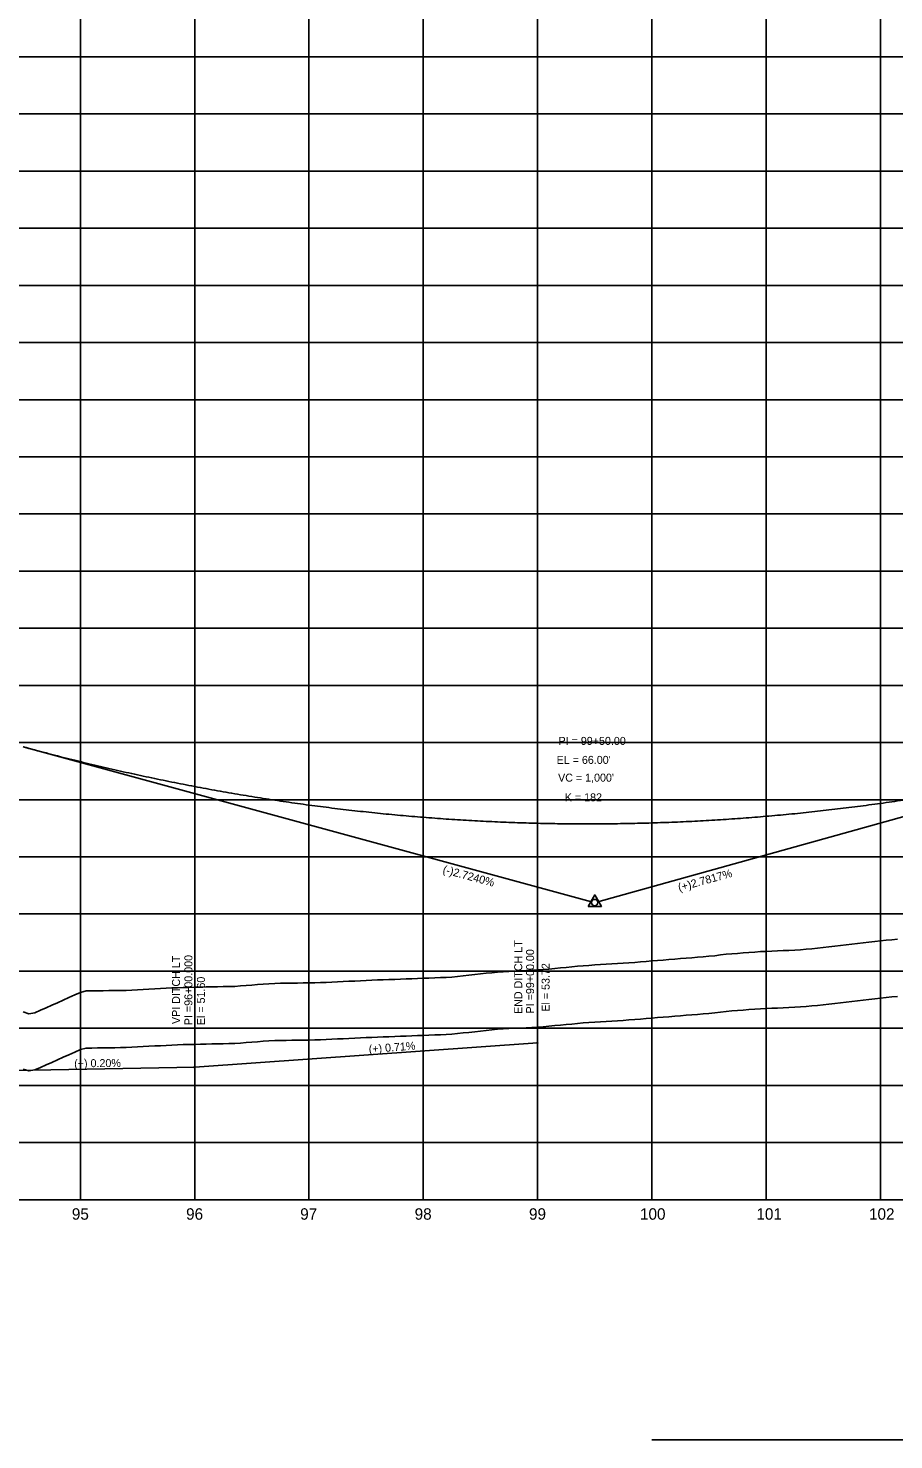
# Model space of a CAD drawing. Extents: x 2345490 to 2436403, y 465165 to 573888.
# Drawn here: x 2389776 to 2390533, y 564066 to 565302 of the extents above; entities that cross this region are included whole.
import ezdxf

# ---------------------------------------------------------------- set-up
doc = ezdxf.new("R2010")
doc.units = 0
for name, color, linetype in [('Old_Level_1', 7, 'Continuous'), ('Old_Level_2', 7, 'Continuous'), ('Old_Level_3', 7, 'Continuous'), ('Old_Level_57', 7, 'Continuous'), ('Old_Level_62', 7, 'Continuous'), ('Old_Level_63', 7, 'Continuous'), ('Prop PFL Text', 7, 'Continuous')]:
    doc.layers.add(name, color=color, linetype=linetype)

msp = doc.modelspace()

# ---------------------------------------------------------------- linework, layer by layer
at = {"layer": 'Old_Level_1'}
for points in [[(2390371.5425, 564439.5035), (2390376.5425, 564440.03), (2390381.5425, 564440.701), (2390386.5425, 564441.3255), (2390391.5425, 564441.699), (2390396.5425, 564442.07225), (2390401.5425, 564442.44575), (2390406.5425, 564442.819), (2390411.5425, 564443.1925), (2390416.5425, 564443.56575), (2390421.5425, 564443.85075), (2390426.5425, 564444.058), (2390431.5425, 564444.2655), (2390436.5425, 564444.473), (2390441.5425, 564444.6805), (2390446.5425, 564444.888), (2390451.5425, 564445.15475), (2390456.5425, 564445.6045), (2390461.5425, 564446.054), (2390466.5425, 564446.5295), (2390471.5425, 564447.11375), (2390476.5425, 564447.698), (2390481.5425, 564448.28225), (2390486.5425, 564448.86675), (2390491.5425, 564449.451), (2390496.5425, 564450.03525), (2390501.5425, 564450.6195), (2390506.5425, 564451.20375), (2390511.5425, 564451.788), (2390516.5425, 564452.37225), (2390521.5425, 564452.9565), (2390526.5425, 564453.529), (2390531.5425, 564453.95725), (2390536.5425, 564454.36375)], [(2389871.5425, 564410.2365), (2389876.5425, 564410.5485), (2389881.5425, 564410.827), (2389886.5425, 564411.0695), (2389891.5425, 564411.312), (2389896.5425, 564411.5545), (2389901.5425, 564411.797), (2389906.5425, 564412.0395), (2389911.5425, 564412.1925), (2389916.5425, 564412.33975), (2389921.5425, 564412.46975), (2389926.5425, 564412.581), (2389931.5425, 564412.692), (2389936.5425, 564412.80325), (2389941.5425, 564412.91175), (2389946.5425, 564412.998), (2389951.5425, 564413.0845), (2389956.5425, 564413.174), (2389961.5425, 564413.5715), (2389966.5425, 564413.96925), (2389971.5425, 564414.36675), (2389976.5425, 564414.76425), (2389981.5425, 564415.16175), (2389986.5425, 564415.55925), (2389991.5425, 564415.75075), (2389996.5425, 564415.88525), (2390001.5425, 564415.95875), (2390006.5425, 564416.032), (2390011.5425, 564416.1055), (2390016.5425, 564416.179), (2390021.5425, 564416.2525), (2390026.5425, 564416.326), (2390031.5425, 564416.4555), (2390036.5425, 564416.68725), (2390041.5425, 564416.919), (2390046.5425, 564417.15075), (2390051.5425, 564417.3825), (2390056.5425, 564417.6145), (2390061.5425, 564417.84625), (2390066.5425, 564418.07875), (2390071.5425, 564418.38475), (2390076.5425, 564418.57825), (2390081.5425, 564418.7715), (2390086.5425, 564418.965), (2390091.5425, 564419.15825), (2390096.5425, 564419.35175), (2390101.5425, 564419.54525), (2390106.5425, 564419.7385), (2390111.5425, 564419.932), (2390116.5425, 564420.12525), (2390121.5425, 564420.31875), (2390126.5425, 564420.51225), (2390131.5425, 564420.7055), (2390136.5425, 564420.899), (2390141.5425, 564421.09225), (2390146.5425, 564421.29325), (2390151.5425, 564421.84775), (2390156.5425, 564422.4005), (2390161.5425, 564422.9535), (2390166.5425, 564423.5065), (2390171.5425, 564424.0595), (2390176.5425, 564424.6125), (2390181.5425, 564425.16525), (2390186.5425, 564425.65475), (2390191.5425, 564425.932), (2390196.5425, 564426.20925), (2390201.5425, 564426.48625), (2390206.5425, 564426.7635), (2390211.5425, 564427.04075), (2390216.5425, 564427.318), (2390221.5425, 564427.595), (2390226.5425, 564427.90175), (2390231.5425, 564428.37525), (2390236.5425, 564428.849), (2390241.5425, 564429.3225), (2390246.5425, 564429.796), (2390251.5425, 564430.2695), (2390256.5425, 564430.74325), (2390261.5425, 564431.21675), (2390266.5425, 564431.585), (2390271.5425, 564431.89975), (2390276.5425, 564432.2145), (2390281.5425, 564432.5295), (2390286.5425, 564432.84425), (2390291.5425, 564433.159), (2390296.5425, 564433.474), (2390301.5425, 564433.812), (2390306.5425, 564434.1725), (2390311.5425, 564434.5825), (2390316.5425, 564434.99275), (2390321.5425, 564435.40275), (2390326.5425, 564435.81275), (2390331.5425, 564436.223), (2390336.5425, 564436.633), (2390341.5425, 564437.043), (2390346.5425, 564437.453), (2390351.5425, 564437.86325), (2390356.5425, 564438.27325), (2390361.5425, 564438.68325), (2390366.5425, 564439.0935), (2390371.5425, 564439.5035)], [(2389771.5425, 564390.865), (2389776.5425, 564389.26775), (2389781.5425, 564390.167), (2389786.5425, 564392.3445), (2389791.5425, 564394.52175), (2389796.5425, 564396.69925), (2389801.5425, 564398.87675), (2389806.5425, 564401.13175), (2389811.5425, 564403.4), (2389816.5425, 564405.6685), (2389821.5425, 564407.93675), (2389826.5425, 564409.18375), (2389831.5425, 564409.2605), (2389836.5425, 564409.32175), (2389841.5425, 564409.383), (2389846.5425, 564409.4445), (2389851.5425, 564409.50575), (2389856.5425, 564409.567), (2389861.5425, 564409.62825), (2389866.5425, 564409.9245), (2389871.5425, 564410.2365)]]:
    msp.add_lwpolyline(points, dxfattribs=at)
at = {"layer": 'Old_Level_2'}
for p, q in [((2390771.5425, 564675.6185), (2390274.192, 564537.27075)), ((2389771.5425, 564672.734), (2390268.88925, 564537.25675))]:
    msp.add_line(p, q, dxfattribs=at)
msp.add_lwpolyline([(2390265.75075, 564533.1055), (2390277.49325, 564533.1055), (2390271.62225, 564543.23125)], close=True, dxfattribs=at)
msp.add_circle((2390271.5425, 564536.534), 2.75, dxfattribs=at)
msp.add_spline([(2389771.5425, 564672.734), (2389791.5425, 564667.396), (2389811.5425, 564662.27825), (2389831.5425, 564657.381), (2389851.5425, 564652.70375), (2389871.5425, 564648.24675), (2389891.5425, 564644.01), (2389911.5425, 564639.9935), (2389931.5425, 564636.19725), (2389951.5425, 564632.621), (2389971.5425, 564629.26525), (2389991.5425, 564626.12975), (2390011.5425, 564623.21425), (2390031.5425, 564620.519), (2390051.5425, 564618.04425), (2390071.5425, 564615.7895), (2390091.5425, 564613.755), (2390111.5425, 564611.94075), (2390131.5425, 564610.34675), (2390151.5425, 564608.973), (2390171.5425, 564607.8195), (2390191.5425, 564606.886), (2390211.5425, 564606.173), (2390231.5425, 564605.68), (2390251.5425, 564605.4075), (2390271.5425, 564605.355), (2390291.5425, 564605.52275), (2390311.5425, 564605.91075), (2390331.5425, 564606.519), (2390351.5425, 564607.3475), (2390371.5425, 564608.39625), (2390391.5425, 564609.66525), (2390411.5425, 564611.1545), (2390431.5425, 564612.86375), (2390451.5425, 564614.7935), (2390471.5425, 564616.94325), (2390491.5425, 564619.31325), (2390511.5425, 564621.90375), (2390531.5425, 564624.71425), (2390551.5425, 564627.745), (2390571.5425, 564630.996), (2390591.5425, 564634.46725), (2390611.5425, 564638.1585), (2390631.5425, 564642.07025), (2390651.5425, 564646.20225), (2390671.5425, 564650.55425), (2390691.5425, 564655.12675), (2390711.5425, 564659.91925), (2390731.5425, 564664.932), (2390751.5425, 564670.165), (2390771.5425, 564675.6185)], degree=3, dxfattribs=at)
at = {"layer": 'Old_Level_3'}
for p, q in [((2389921.5425, 564392.534), (2390221.5425, 564413.734)), ((2389101.5425, 564376.534), (2389921.5425, 564392.534))]:
    msp.add_line(p, q, dxfattribs=at)
for centre in [(2390221.5425, 564413.734), (2389921.5425, 564392.534)]:
    msp.add_circle(centre, 0.5, dxfattribs=at)
at = {"layer": 'Old_Level_57'}
for p, q in [((2389821.54225, 564276.534), (2389821.54225, 566615.2835)), ((2389921.5425, 564276.534), (2389921.5425, 566615.2835)), ((2390021.54225, 564276.534), (2390021.54225, 566615.2835)), ((2390121.54225, 564276.534), (2390121.54225, 566615.2835)), ((2390221.54225, 564276.534), (2390221.54225, 566615.2835)), ((2390321.5425, 564276.534), (2390321.5425, 566615.2835)), ((2390421.54225, 564276.534), (2390421.54225, 566615.2835)), ((2390521.54225, 564276.534), (2390521.54225, 566615.2835)), ((2381271.5425, 565276.534), (2410861.12275, 565276.534)), ((2381271.5425, 565226.534), (2410861.12275, 565226.534)), ((2381271.5425, 565176.534), (2410861.12275, 565176.534)), ((2381271.5425, 565126.534), (2410861.12275, 565126.534)), ((2381271.5425, 565076.534), (2410861.12275, 565076.534)), ((2381271.5425, 565026.534), (2410861.12275, 565026.534)), ((2381271.5425, 564976.534), (2410861.12275, 564976.534)), ((2381271.5425, 564926.534), (2410861.12275, 564926.534)), ((2381271.5425, 564876.534), (2410861.12275, 564876.534)), ((2381271.5425, 564826.534), (2410861.12275, 564826.534)), ((2381271.54275, 564776.534), (2410861.123, 564776.534)), ((2381271.5425, 564726.534), (2410861.12275, 564726.534)), ((2381271.54275, 564676.534), (2410861.123, 564676.534)), ((2381271.5425, 564626.534), (2410861.12275, 564626.534)), ((2381271.54275, 564576.534), (2410861.123, 564576.534)), ((2381271.5425, 564526.534), (2410861.12275, 564526.534)), ((2381271.54275, 564476.534), (2410861.123, 564476.534)), ((2381271.5425, 564426.534), (2410861.12275, 564426.534)), ((2381271.54275, 564376.534), (2410861.123, 564376.534)), ((2381271.5425, 564326.534), (2410861.12275, 564326.534)), ((2381271.54275, 564276.534), (2410861.123, 564276.534))]:
    msp.add_line(p, q, dxfattribs=at)
at = {"layer": 'Old_Level_62'}
msp.add_line((2390321.5425, 564066.4875), (2391321.5425, 564066.4875), dxfattribs=at)
at = {"layer": 'Old_Level_63'}
msp.add_line((2381321.5425, 564276.534), (2406689.937, 564276.534), dxfattribs=at)
for points in [[(2390371.5425, 564489.50325), (2390376.5425, 564490.02975), (2390381.5425, 564490.70075), (2390386.5425, 564491.32525), (2390391.5425, 564491.69875), (2390396.5425, 564492.072), (2390401.5425, 564492.4455), (2390406.5425, 564492.81875), (2390411.5425, 564493.19225), (2390416.5425, 564493.5655), (2390421.5425, 564493.8505), (2390426.5425, 564494.05775), (2390431.5425, 564494.26525), (2390436.5425, 564494.47275), (2390441.5425, 564494.68025), (2390446.5425, 564494.88775), (2390451.5425, 564495.1545), (2390456.5425, 564495.60425), (2390461.5425, 564496.05375), (2390466.5425, 564496.52925), (2390471.5425, 564497.1135), (2390476.5425, 564497.69775), (2390481.5425, 564498.282), (2390486.5425, 564498.8665), (2390491.5425, 564499.45075), (2390496.5425, 564500.035), (2390501.5425, 564500.61925), (2390506.5425, 564501.2035), (2390511.5425, 564501.78775), (2390516.5425, 564502.372), (2390521.5425, 564502.95625), (2390526.5425, 564503.52875), (2390531.5425, 564503.957), (2390536.5425, 564504.3635)], [(2389871.5425, 564460.23625), (2389876.5425, 564460.54825), (2389881.5425, 564460.82675), (2389886.5425, 564461.06925), (2389891.5425, 564461.31175), (2389896.5425, 564461.55425), (2389901.5425, 564461.79675), (2389906.5425, 564462.03925), (2389911.5425, 564462.19225), (2389916.5425, 564462.3395), (2389921.5425, 564462.4695), (2389926.5425, 564462.58075), (2389931.5425, 564462.69175), (2389936.5425, 564462.803), (2389941.5425, 564462.9115), (2389946.5425, 564462.99775), (2389951.5425, 564463.08425), (2389956.5425, 564463.17375), (2389961.5425, 564463.57125), (2389966.5425, 564463.969), (2389971.5425, 564464.3665), (2389976.5425, 564464.764), (2389981.5425, 564465.1615), (2389986.5425, 564465.559), (2389991.5425, 564465.7505), (2389996.5425, 564465.885), (2390001.5425, 564465.9585), (2390006.5425, 564466.03175), (2390011.5425, 564466.10525), (2390016.5425, 564466.17875), (2390021.5425, 564466.25225), (2390026.5425, 564466.32575), (2390031.5425, 564466.45525), (2390036.5425, 564466.687), (2390041.5425, 564466.91875), (2390046.5425, 564467.1505), (2390051.5425, 564467.38225), (2390056.5425, 564467.61425), (2390061.5425, 564467.846), (2390066.5425, 564468.0785), (2390071.5425, 564468.3845), (2390076.5425, 564468.578), (2390081.5425, 564468.77125), (2390086.5425, 564468.96475), (2390091.5425, 564469.158), (2390096.5425, 564469.3515), (2390101.5425, 564469.545), (2390106.5425, 564469.73825), (2390111.5425, 564469.93175), (2390116.5425, 564470.125), (2390121.5425, 564470.3185), (2390126.5425, 564470.512), (2390131.5425, 564470.70525), (2390136.5425, 564470.89875), (2390141.5425, 564471.092), (2390146.5425, 564471.293), (2390151.5425, 564471.8475), (2390156.5425, 564472.40025), (2390161.5425, 564472.95325), (2390166.5425, 564473.50625), (2390171.5425, 564474.05925), (2390176.5425, 564474.61225), (2390181.5425, 564475.165), (2390186.5425, 564475.6545), (2390191.5425, 564475.93175), (2390196.5425, 564476.209), (2390201.5425, 564476.486), (2390206.5425, 564476.76325), (2390211.5425, 564477.0405), (2390216.5425, 564477.31775), (2390221.5425, 564477.59475), (2390226.5425, 564477.9015), (2390231.5425, 564478.375), (2390236.5425, 564478.84875), (2390241.5425, 564479.32225), (2390246.5425, 564479.79575), (2390251.5425, 564480.26925), (2390256.5425, 564480.743), (2390261.5425, 564481.2165), (2390266.5425, 564481.58475), (2390271.5425, 564481.8995), (2390276.5425, 564482.21425), (2390281.5425, 564482.52925), (2390286.5425, 564482.844), (2390291.5425, 564483.15875), (2390296.5425, 564483.47375), (2390301.5425, 564483.81175), (2390306.5425, 564484.17225), (2390311.5425, 564484.58225), (2390316.5425, 564484.9925), (2390321.5425, 564485.4025), (2390326.5425, 564485.8125), (2390331.5425, 564486.22275), (2390336.5425, 564486.63275), (2390341.5425, 564487.04275), (2390346.5425, 564487.45275), (2390351.5425, 564487.863), (2390356.5425, 564488.273), (2390361.5425, 564488.683), (2390366.5425, 564489.09325), (2390371.5425, 564489.50325)], [(2389771.5425, 564440.86475), (2389776.5425, 564439.2675), (2389781.5425, 564440.16675), (2389786.5425, 564442.34425), (2389791.5425, 564444.5215), (2389796.5425, 564446.699), (2389801.5425, 564448.8765), (2389806.5425, 564451.1315), (2389811.5425, 564453.39975), (2389816.5425, 564455.66825), (2389821.5425, 564457.9365), (2389826.5425, 564459.1835), (2389831.5425, 564459.26025), (2389836.5425, 564459.3215), (2389841.5425, 564459.38275), (2389846.5425, 564459.44425), (2389851.5425, 564459.5055), (2389856.5425, 564459.56675), (2389861.5425, 564459.628), (2389866.5425, 564459.92425), (2389871.5425, 564460.23625)]]:
    msp.add_lwpolyline(points, dxfattribs=at)
at = {"layer": 'Prop PFL Text'}
for p, q in [((2390221.5425, 564413.734), (2390221.5425, 564521.0307)), ((2389921.5425, 564392.534), (2389921.5425, 564497.73258))]:
    msp.add_line(p, q, dxfattribs=at)

# ---------------------------------------------------------------- texts
at = {"layer": 'Old_Level_2'}
for s, height, p in [('PI = 99+50.00', 7.0000005, (2390239.91525, 564674.473)), ("EL = 66.00'", 7.0000005, (2390238.22875, 564657.847)), ("VC = 1,000'", 7.0000005, (2390239.50175, 564642.3165)), ('K = 182', 7.000001, (2390245.404, 564625.108))]:
    msp.add_text(s, height=height, dxfattribs=at).set_placement(p)
for s, rotation, p in [('(-)2.7240%', 344.76233611, (2390138.06369, 564562.50171)), ('(+)2.7817%', 15.54491944, (2390345.55068, 564546.14393))]:
    msp.add_text(s, height=7.000001, rotation=rotation, dxfattribs=at).set_placement(p)
at = {"layer": 'Old_Level_3'}
for s, height, rotation, p in [('END DITCH LT', 7.0000005, 90, (2390208.13251, 564439.06625)), ('PI =99+00.00', 7.0000005, 90, (2390218.50001, 564439.52378)), ('VPI DITCH LT', 7.0000005, 90, (2389908.71482, 564430.23194)), ('PI =96+00.000', 7.0000005, 90, (2389919.5425, 564429.2476)), ('El = 53.72', 7.000001, 90, (2390232.10623, 564441.08751)), ('El = 51.60', 7.000001, 90, (2389930.5425, 564429.2476)), ('(+) 0.71%', 7, 4.39870556, (2390074.11477, 564404.77137)), ('(+) 0.20%', 7.000001, 0.44676187, (2389816.14393, 564392.36072))]:
    msp.add_text(s, height=height, rotation=rotation, dxfattribs=at).set_placement(p)
at = {"layer": 'Old_Level_62'}
for s, p in [('95', (2389814.0865, 564259.034)), ('96', (2389914.0275, 564259.034)), ('97', (2390013.885, 564259.034)), ('98', (2390114.01075, 564259.034)), ('99', (2390214.053, 564259.034)), ('100', (2390311.1715, 564259.034)), ('101', (2390413.01075, 564259.034)), ('102', (2390511.55925, 564259.034))]:
    msp.add_text(s, height=10.000001, dxfattribs=at).set_placement(p)

doc.saveas('drawing.dxf')
